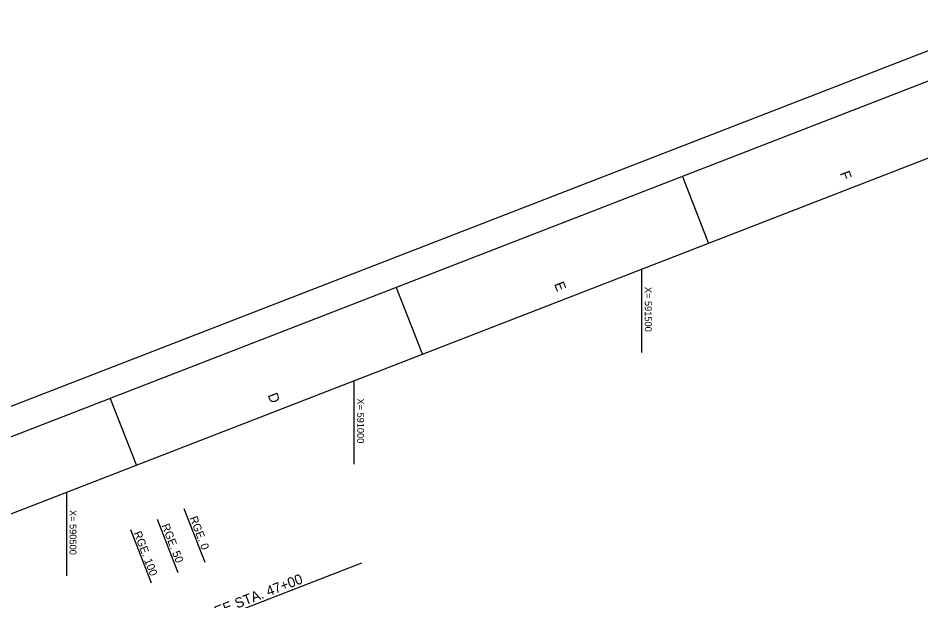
# Model space of a CAD drawing. Extents: x 588973 to 593734, y 821498 to 826830.
# Drawn here: x 590416 to 591985, y 825816 to 826830 of the extents above; entities that cross this region are included whole.
import ezdxf

# ---------------------------------------------------------------- set-up
doc = ezdxf.new("R2010")
doc.units = 0
for name, color, linetype in [('G-ANNO-NPLT', 7, 'Continuous'), ('G-ANNO-TTLB', 7, 'Continuous'), ('V-ALGN-TEXT', 7, 'Continuous'), ('V-ANNO-MATC', 7, 'Continuous'), ('V-ANNO-MATC-IDEN', 7, 'Continuous'), ('V-TOPO-COOR-STAT', 7, 'Continuous')]:
    doc.layers.add(name, color=color, linetype=linetype)

msp = doc.modelspace()

# ---------------------------------------------------------------- linework, layer by layer
at = {"layer": 'G-ANNO-NPLT'}
msp.add_lwpolyline([(592142.7, 826829.7), (593734.3, 822727.7), (590564.5, 821497.8), (588973, 825599.9)], close=True, dxfattribs=at)
at = {"layer": 'G-ANNO-TTLB'}
for p, q in [((591570.2, 826554), (591615.4, 826437.4)), ((591073, 826361.1), (591118.3, 826244.5)), ((590575.9, 826168.2), (590621.1, 826051.6))]:
    msp.add_line(p, q, dxfattribs=at)
for points in [[(589037.7, 825571.4), (590593, 821562.5), (593669.6, 822756.2), (592114.2, 826765)], [(593604.9, 822784.7), (592112.8, 826630.4), (589129.5, 825472.9), (590621.6, 821627.2)]]:
    msp.add_lwpolyline(points, close=True, dxfattribs=at)
at = {"layer": 'V-ALGN-TEXT'}
for p, q in [((590703.9, 825976.5), (590740.1, 825883.3)), ((590657.3, 825958.4), (590693.5, 825865.2)), ((590610.7, 825940.3), (590646.9, 825847.1))]:
    msp.add_line(p, q, dxfattribs=at)
at = {"layer": 'V-ANNO-MATC'}
msp.add_line((591012.7, 825881.8), (590445.6, 825661.8), dxfattribs=at)
at = {"layer": 'V-TOPO-COOR-STAT'}
for p, q in [((591500, 826247.8), (591500, 826392.6)), ((591000, 826053.8), (591000, 826198.6)), ((590500, 825859.8), (590500, 826004.6))]:
    msp.add_line(p, q, dxfattribs=at)

# ---------------------------------------------------------------- texts
at = {"layer": 'G-ANNO-TTLB'}
for s, p in [('F', (591843.8, 826559.8)), ('E', (591347.1, 826367.2)), ('D', (590849.2, 826173.9))]:
    msp.add_text(s, height=17.5, rotation=291.2052, dxfattribs=at).set_placement(p)
at = {"layer": 'V-ALGN-TEXT'}
for s, p in [('RGE. 0', (590713.3, 825960.2)), ('RGE. 50', (590664.7, 825947.1)), ('RGE. 100', (590616.1, 825934.1))]:
    msp.add_text(s, height=13.92, rotation=291.2052, dxfattribs=at).set_placement(p)
at = {"layer": 'V-ANNO-MATC-IDEN'}
msp.add_text('MATCHLINE SHEET NO. 029 LEE STA. 47+00', height=17.52, rotation=21.2052, dxfattribs=at).set_placement((590450.2, 825668.2))
at = {"layer": 'V-TOPO-COOR-STAT'}
for s, p in [('X= 591500', (591505, 826362.1)), ('X= 591000', (591005, 826168.1)), ('X= 590500', (590505, 825974.1))]:
    msp.add_text(s, height=12, rotation=270, dxfattribs=at).set_placement(p)

doc.saveas('drawing.dxf')
